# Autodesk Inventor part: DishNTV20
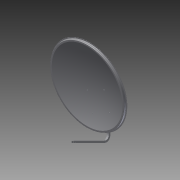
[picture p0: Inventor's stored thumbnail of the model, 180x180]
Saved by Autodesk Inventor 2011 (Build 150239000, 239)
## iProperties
Created: 2014-09
Part Number: DishNTV20
Document SubType Name: Modeling
Designer: Evgeny
Density: 1 g/cm^3
Author: Evgeny
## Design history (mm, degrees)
sketch "Эскиз1"
  geometry: C1 r 300 at (0, 0); 1 further point
  constraints: 1 centre point, 1 coincident
  dimensions: "d0" = 600 diameter of C1
extrude "Выдавливание1" new body sketch "Эскиз1" distance "d1" = 400; taper "d2" = 0 deg
sketch "Эскиз2"
  geometry: L1 (-300, -380)-(294.596, -380); L2 (300, -78)-(-300, -380); L3 (300, -78)-(300, 0); L4 (300, 0)-(-300, 0); L5 (-300, 0)-(-300, -380); 6 further points
  constraints: 10 end point, 2 perpendicular, 1 parallel, 7 other
  dimensions: "d42" = 100 horizontal distance of point (-200, -371.6) L1.start; "d43" = 200 horizontal distance of point (-100, -346.5) L1.start; "d44" = 300 horizontal distance of point (0, -304.5) L1.start; "d45" = 400 horizontal distance of point (100, -245.8) L1.start; "d46" = 500 horizontal distance of point (200, -170.3) L1.start; "d47" = 600 horizontal distance of L2.start L1.start; "d48" = 8.4 distance from line of point (-200, -371.6) L1; "d49" = 33.5 distance from line of L1 point (-100, -346.5); "d50" = 75.5 distance from line of L1 point (0, -304.5); "d51" = 134.2 distance from line of L1 point (100, -245.8); "d52" = 209.7 distance from line of L1 point (200, -170.3); "d53" = 302 distance from line of L2.start L1; "d54" = 671.7172 distance of L2.start L1.start (derived); "d55" = 380 distance from line of L4 L1.start; "d56" = 0 distance from line of L4 point (0, 0); "d57" = 600 distance between parallel lines of L3 L5; "d58" = 78 distance from line of L4 L2.start (derived); "d71" = 116.718 deg angle of L2 L3 (derived)
revolve "Вращение2" sketch "Эскиз2" stored, may be unused: angle "d59" = 90 deg
feature "Оболочка2" dims "d60" = 1
sketch "Эскиз3"
  geometry: L1 (300, -78)-(310.719, -72.604); L2 (314.747, -73.935)-(321.492, -87.333); L3 (324.177, -88.221)-(331.323, -84.624); L4 (331.323, -84.624)-(331.773, -85.517); L5 (331.773, -85.517)-(324.627, -89.114); L6 (320.598, -87.783)-(313.971, -74.617); L7 (311.285, -73.73)-(300, -79.411); L8 (300, -79.411)-(300, -78); A1 r 2 centre (323.278, -86.434) between (321.492, -87.333) and (324.177, -88.221); A2 r 2 centre (312.184, -75.516) between (313.971, -74.617) and (311.285, -73.73); A3 r 3 centre (323.278, -86.434) between (320.598, -87.783) and (324.627, -89.114); A4 r 3 centre (312.067, -75.284) between (314.747, -73.935) and (310.719, -72.604); 2 further points
  constraints: 16 end point, 8 point on circle, 8 tangent, 5 parallel, 4 centre point, 2 equal radius, 2 point on line, 1 perpendicular, 1 vertical
  dimensions: "d61" = 20 distance between parallel lines of L3 L1; "d62" = 300 distance from line of L8 point (0, 0); "d63" = 78 vertical distance of point (0, 0) L1.start; "d65" = 15 distance of L1.start point (313.398, -71.256); "d66" = 1.26 distance between parallel lines of L7 L1; "d67" = 1 distance between parallel lines of L6 L2; "d68" = 1 distance between parallel lines of L5 L3; "d69" = 2 radius of A1; "d70" = 3 radius of A3; "d72" = 116.72 deg angle of L1 L8; "d73" = 10 distance between parallel lines of L4 L2
sketch "3D эскиз1"
feature "Сдвиг1" sketch "Эскиз3", "3D эскиз1" dims "d74" = 0
fillet "Сопряжение1" dims "d98" = 2
sketch "Эскиз8"
  geometry: L1 (0, -327)-(-308.091, -430.402); L2 (-374, -383)-(-374, -107); L3 (-374, -107)-(-374, -92); L4 (-374, -67)-(-346.049, -31.733); L5 (0, -306)-(-346.049, -31.733); L6 (-305.894, -63.559)-(-346.049, -31.733); A1 r 50 centre (-324, -383) between (-374, -383) and (-308.091, -430.402); 1 further point
  constraints: 12 end point, 2 point on circle, 2 point on line, 2 tangent, 1 centre point, 1 collinear, 1 perpendicular, 1 vertical
  dimensions: "d99" = 50 radius of A1; "d100" = 327 distance of L1.start point (0, 0); "d101" = 383 vertical distance of A1.centre point (0, 0); "d129" = 324 horizontal distance of A1.centre point (0, 0); "d130" = 107 vertical distance of point (0, 0) L2.end; "d131" = 374 horizontal distance of point (0, 0) L2.end (derived); "d132" = 15 distance of L3.end L2.end; "d167" = 45 distance of L4.start L4.end; "d168" = 25 distance of L4.start L3.end; "d179" = 141.601 deg angle of L2 L4
node "РабПлоскость2"
sketch "Эскиз9" dims "d56" = 0
  geometry: L1 (-9.009, 8)-(8.991, 8); L2 (9.991, 7)-(9.991, -7); L3 (8.991, -8)-(-9.009, -8); L4 (-10.009, -7)-(-10.009, 7); L5 (-9.009, 7)-(8.991, 7); L6 (8.991, 7)-(8.991, -7); L7 (8.991, -7)-(-9.009, -7); L8 (-9.009, -7)-(-9.009, 7); A1 r 1 centre (-9.009, 7) between (-9.009, 8) and (-10.009, 7); A2 r 1 centre (8.991, 7) between (9.991, 7) and (8.991, 8); A3 r 1 centre (8.991, -7) between (8.991, -8) and (9.991, -7); A4 r 1 centre (-9.009, -7) between (-10.009, -7) and (-9.009, -8); 5 further points
  constraints: 16 end point, 8 point on circle, 8 point on line, 8 tangent, 4 centre point, 4 parallel, 3 equal radius, 2 horizontal, 2 perpendicular
  dimensions: "d105" = 1 radius of A1; "d106" = 16 distance between parallel lines of L3 L1; "d107" = 20 distance between parallel lines of L2 L4; "d108" = 14 distance between parallel lines of L5 L7; "d109" = 18 distance between parallel lines of L6 L8; "d110" = 1 distance between parallel lines of L3 L7; "d111" = 1 distance between parallel lines of L4 L8
feature "Сдвиг2" sketch "Эскиз9" dims "d104" = 0
hole "Отверстие1" diameter "d135" = 6; stored, may be unused: countersink angle "d139" = 90 deg, drill point angle "d141" = 118 deg; dims "d133" = 7, "d134" = 15, "d136" = 6, "d137" = 4, "d138" = 2, "d140" = 8
sketch "Эскиз11"
  geometry: L1 (0, 0)-(18, 0) reference; L2 (0, 0)-(0, -324.98) reference; L3 (-83, 0)-(97, 0); L4 (102, -5)-(102, -35); L5 (97, -40)-(-83, -40); L6 (-88, -35)-(-88, -5); L7 (-83, -160)-(97, -160); L8 (102, -165)-(102, -195); L9 (97, -200)-(-83, -200); L10 (-88, -195)-(-88, -165); C1 r 5 at (7, -180) reference; C2 r 5 at (7, -20) reference; C3 r 5 at (-73, -20); C4 r 5 at (87, -20); C5 r 5 at (87, -180); C6 r 5 at (-73, -180); A1 r 5 centre (-83, -5) between (-83, 0) and (-88, -5); A2 r 5 centre (-83, -35) between (-88, -35) and (-83, -40); A3 r 5 centre (97, -35) between (97, -40) and (102, -35); A4 r 5 centre (97, -5) between (102, -5) and (97, 0); A5 r 5 centre (-83, -165) between (-83, -160) and (-88, -165); A6 r 5 centre (-83, -195) between (-88, -195) and (-83, -200); A7 r 5 centre (97, -195) between (97, -200) and (102, -195); A8 r 5 centre (97, -165) between (102, -165) and (97, -160); 9 further points
  constraints: 16 end point, 16 point on circle, 16 point on line, 16 tangent, 12 centre point, 7 equal radius, 4 parallel, 2 collinear, 2 horizontal, 2 perpendicular
  dimensions: "d142" = 40 distance between parallel lines of L5 L3; "d143" = 40 distance between parallel lines of L5 L1; "d146" = 160 distance between parallel lines of L7 L3; "d147" = 40 distance between parallel lines of L9 L7; "d149" = 10 diameter of C3; "d155" = 73 distance from line of C3.centre L2; "d156" = 160 distance of C4.centre C3.centre; "d157" = 190 distance between parallel lines of L4 L6; "d158" = 15 distance from line of L6 C3.centre; "d159" = 20 distance from line of L3 C3.centre; "d160" = 20 distance from line of C6.centre L7; "d161" = 5 radius of A1
extrude "Выдавливание3" join sketch "Эскиз11" distance "d152" = 2; taper "d153" = 0 deg
extrude "Выдавливание4" join sketch "Эскиз11" distance "d162" = 17; taper "d164" = 0 deg; dims "d163" = 6, "d165" = 0
fillet "Сопряжение3" dims "d166" = 1
node "Твердое тело1"
